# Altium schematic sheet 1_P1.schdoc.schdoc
size 309 x 223 mm; Symbol: Sheet-Symbol_A4; Device: Sheet-Symbol_A4; Company: 嘉立创EDA; Version: V1.0; Page Size: A4; @Project Name: ESP32C3电流表; @Page Count: 1; @Update Date: 2024-03-28; @Create Date: 2024-03-27; @Schematic Name: Schematic1; @Page No: 1; @Page Name: P1
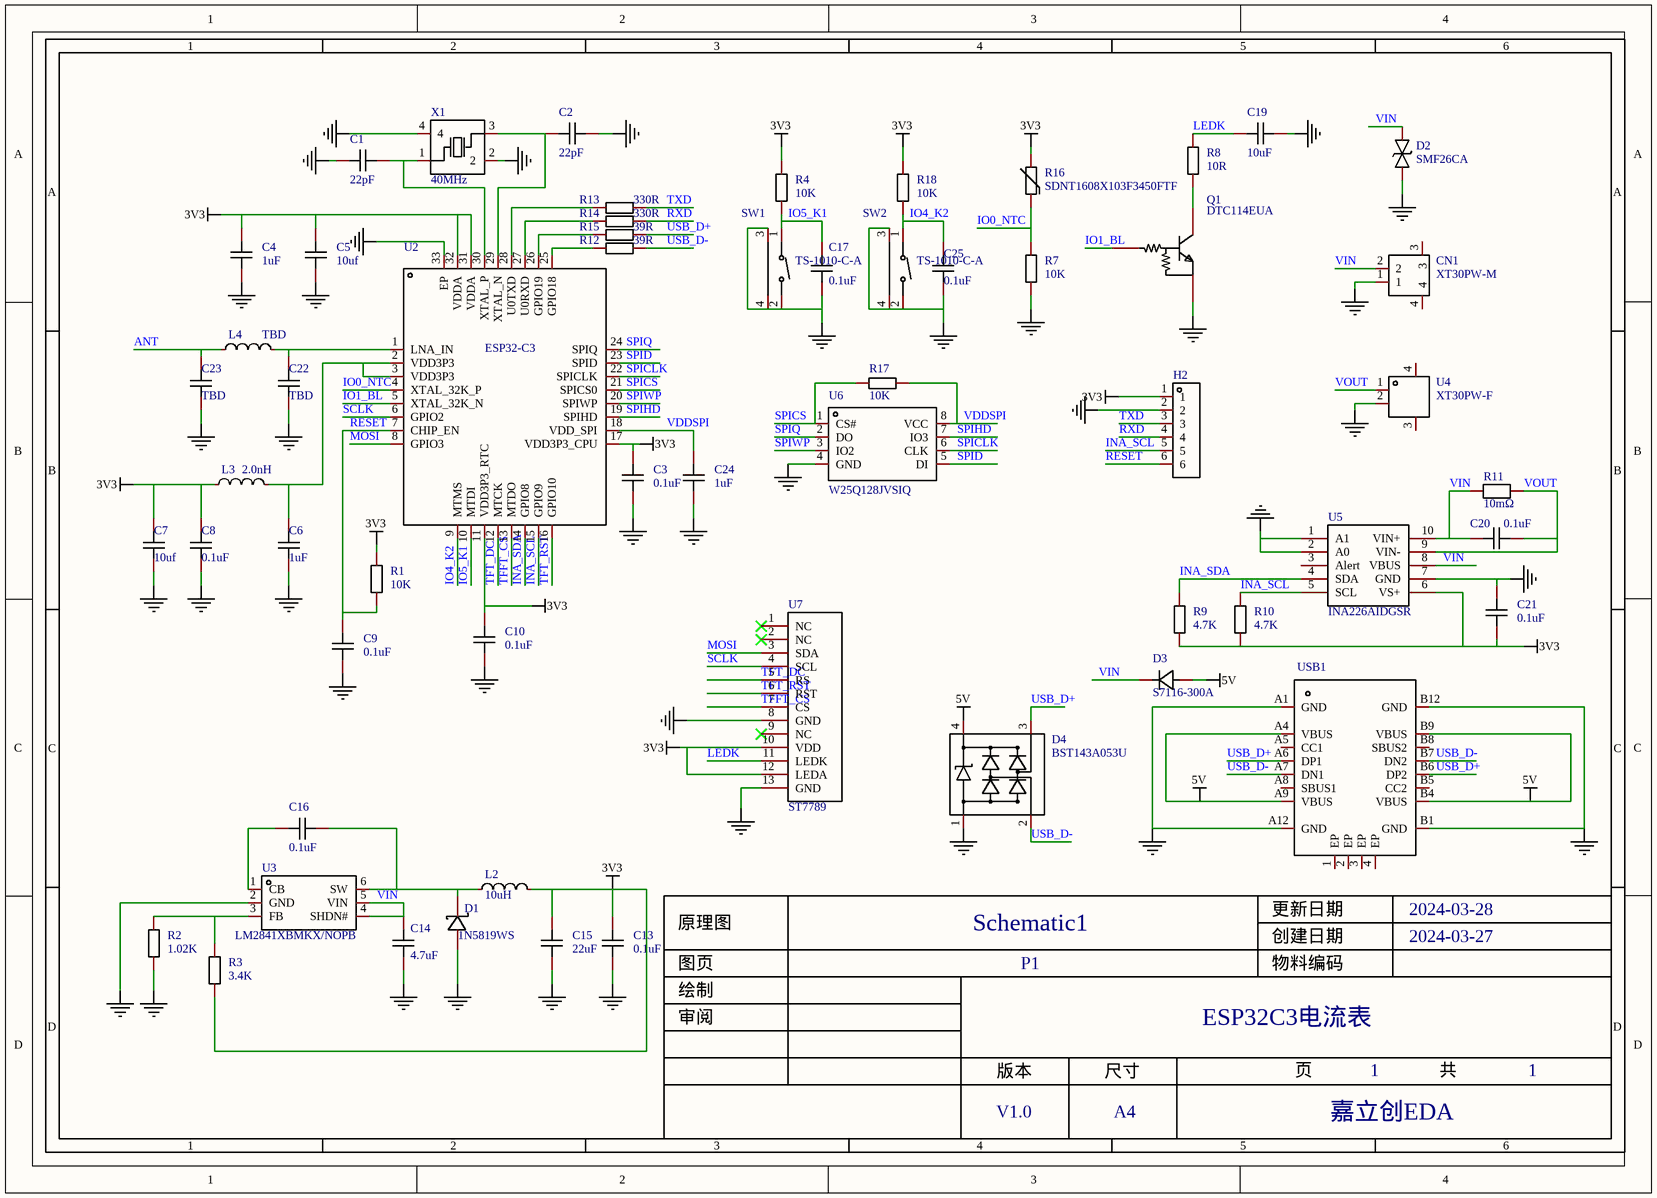
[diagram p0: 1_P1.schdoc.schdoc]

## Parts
C1  22pF  [C0603]
C2  22pF  [C0603]
C3  0.1uF  [C0603]
C4  1uF  [C0603]
C5  10uf  [C0603]
C6  1uF  [C0603]
C7  10uf  [C0603]
C8  0.1uF  [C0603]
C9  0.1uF  [C0603]
C10  0.1uF  [C0603]
C13  0.1uF  [C0603]
C14  4.7uF  [C0805]
C15  22uF  [C0805]
C16  0.1uF  [C0603]
C17  0.1uF  [C0603]
C19  10uF  [C0603]
C20  0.1uF  [C0603]
C21  0.1uF  [C0603]
C22  TBD  [C0603]
C23  TBD  [C0603]
C24  1uF  [C0603]
C25  0.1uF  [C0603]
CN1  XT30PW-M  [CONN-TH_XT30PW-M]
D1  1N5819WS  [SOD-323_L1.8-W1.3-LS2.5-RD]
D2  SMF26CA  [SOD-123_L2.8-W1.8-LS3.7-BI]
D3  S7116-300A  [SOD-323_L1.7-W1.3-LS2.5-RD]
D4  BST143A053U  [SOT-143_L2.9-W1.3-P1.92-LS2.3-BR]
H2  HDR-F_2.54_1x6P  [HDR-TH_6P-P2.54-V-F]  (value not drawn)
L2  10uH  [IND-SMD_L2.5-W2.0_FHD252012S-6R8MT]
L3  2.0nH  [L0603]
L4  TBD  [L0603]
Q1  DTC114EUA  [SOT-323-3_L2.0-W1.3-P1.30-LS2.1-BR]
R1  10K  [R0603]
R2  1.02K  [R0603]
R3  3.4K  [R0603]
R4  10K  [R0603]
R7  10K  [R0603]
R8  10R  [R0603]
R9  4.7K  [R0603]
R10  4.7K  [R0603]
R11  10mΩ  [R2512]
R12  39R  [R0603]
R13  330R  [R0603]
R14  330R  [R0603]
R15  39R  [R0603]
R16  SDNT1608X103F3450FTF  [R0603]
R17  10K  [R0603]
R18  10K  [R0603]
SW1  TS-1010-C-A  [KEY-SMD_TX-1010-X-X]
SW2  TS-1010-C-A  [KEY-SMD_TX-1010-X-X]
U2  ESP32-C3  [QFN-32_L5.0-W5.0-P0.50-TL-EP3.7]
U3  LM2841XBMKX/NOPB  [SOT-23-6_L2.9-W1.6-P0.95-LS2.8-BR]
U4  XT30PW-F  [CONN-TH_XT30PW-F-1]
U5  INA226AIDGSR  [MSOP-10_L3.0-W3.0-P0.50-LS5.0-BL]
U6  W25Q128JVSIQ  [SOIC-8_L5.3-W5.3-P1.27-LS8.0-BL]
U7  ST7789  [ST7789]
USB1  USB_TYPE-C-16P  [USB_TYPE-C-16P]  (value not drawn)
X1  40MHz  [OSC-SMD_4P-L3.2-W2.5-BL]

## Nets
3V3: C3.2 C4.2 C5.2 C7.2 C8.2 C10.2 C13.2 C15.2 C21.2 H2.1 L2.2 L3.1 R1.1 R3.1 R4.2 R9.1 R10.1 R16.2 R18.2 U2.11(VDD3P3_RTC) U2.17(VDD3P3_CPU) U2.31(VDDA) U2.32(VDDA) U5.6(VS+) U7.10(VDD) U7.12(LEDA)
5V: D3.2(A) D4.4 USB1.A4(VBUS) USB1.A9(VBUS) USB1.B4(VBUS) USB1.B9(VBUS)
GND: C1.1 C2.2 C3.1 C4.1 C5.1 C6.1 C7.1 C8.1 C9.2 C10.1 C13.1 C14.1 C15.1 C17.1 C19.1 C21.1 C22.1 C23.1 C24.1 C25.1 CN1.1 D1.2(A) D2.1 D4.1 H2.2 Q1.2(GND) R2.1 R7.1 SW1.2 SW1.3 SW1.4 SW2.2 SW2.3 SW2.4 U2.33(EP) U3.2(GND) U4.2 U5.1(A1) U5.2(A0) U5.7(GND) U6.4(GND) U7.8(GND) U7.13(GND) USB1.A1(GND) USB1.A12(GND) USB1.B1(GND) USB1.B12(GND) X1.2 X1.4
ANT: C23.2 L4.1
INA_SCL: H2.5 R10.2 U2.15(GPIO9) U5.5(SCL)
INA_SDA: R9.2 U2.14(GPIO8) U5.4(SDA)
IO0_NTC: R7.2 R16.1 U2.4(XTAL_32K_P)
IO1_BL: Q1.1(IN) U2.5(XTAL_32K_N)
IO4_K2: C25.2 R18.1 SW2.1 U2.9(MTMS)
IO5_K1: C17.2 R4.1 SW1.1 U2.10(MTDI)
LEDK: C19.2 R8.2 U7.11(LEDK)
MOSI: U2.8(GPIO3) U7.3(SDA)
RESET: C9.1 H2.6 R1.2 U2.7(CHIP_EN)
RXD: H2.4 R14.1
SCLK: U2.6(GPIO2) U7.4(SCL)
SPICLK: U2.22(SPICLK) U6.6(CLK)
SPICS: R17.1 U2.21(SPICS0) U6.1(CS#)
SPID: U2.23(SPID) U6.5(DI)
SPIHD: U2.19(SPIHD) U6.7(IO3)
SPIQ: U2.24(SPIQ) U6.2(DO)
SPIWP: U2.20(SPIWP) U6.3(IO2)
TFFT_CS: U2.13(MTDO) U7.7(CS)
TFT_DC: U2.12(MTCK) U7.5(RS)
TFT_RST: U2.16(GPIO10) U7.6(RST)
TXD: H2.3 R13.1
USB_D+: D4.3 R15.1 USB1.A6(DP1) USB1.B6(DP2)
USB_D-: D4.2 R12.1 USB1.A7(DN1) USB1.B7(DN2)
VDDSPI: C24.2 R17.2 U2.18(VDD_SPI) U6.8(VCC)
VIN: C14.2 C20.2 CN1.2 D2.2 D3.1(K) R11.1 U3.4(SHDN#) U3.5(VIN) U5.8(VBUS) U5.10(VIN+)
VOUT: C20.1 R11.2 U4.1 U5.9(VIN-)
NetC1_2: C1.2 U2.30(XTAL_P) X1.1(OSC1)
NetC2_1: C2.1 U2.29(XTAL_N) X1.3(OSC2)
NetC6_2: C6.2 L3.2 U2.2(VDD3P3) U2.3(VDD3P3)
NetC16_1: C16.1 D1.1(K) L2.1 U3.6(SW)
NetC16_2: C16.2 U3.1(CB)
NetC22_2: C22.2 L4.2 U2.1(LNA_IN)
NetQ1_3: Q1.3(OUT) R8.1
NetR2_2: R2.2 R3.2 U3.3(FB)
NetR12_2: R12.2 U2.25(GPIO18)
NetR13_2: R13.2 U2.28(U0TXD)
NetR14_2: R14.2 U2.27(U0RXD)
NetR15_2: R15.2 U2.26(GPIO19)

Not connected (* = marked no-connect by the designer): CN1 3 4; U4 3 4; U5 3(Alert); U7 1(NC)* 2(NC)* 9(NC)*; USB1 1(EP) 2(EP) 3(EP) 4(EP) A5(CC1) A8(SBUS1) B5(CC2) B8(SBUS2)

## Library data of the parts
C1-C10 C13 C16 C17 C19-C25 = CAP_0603: Symbol: CapAcitance; Convert to PCB: yes
C14 C15 = CAP_0805: Symbol: CapAcitance; Convert to PCB: yes
CN1 = XT30PW-M: Manufacturer: AMASS(艾迈斯); Add into BOM: yes; Brand: 艾迈斯; RatedVoltage: DC 500V; InterfaceType: 公头; RatedCurrent: 15A; RecommendedWireGauge: 16/18/20AWG; contact resistance: 1.2mΩ; specifications: 2pin; Description: 类别:-;类型1:-;
D1 = 1N5819WS_C191023: Manufacturer: Hottech(合科泰); Add into BOM: yes; Forward Voltage (Vf@If): 600mV@1A; Reverse Voltage (Vr): 40V; Average Rectified Current (Io): 1A; Description: 正向压降(Vf):600mV@1A;直流反向耐压(Vr):40V;平均整流电流(Io):1A;
D2 = SMF26CA_C435495: Manufacturer: AnBon(安邦); Add into BOM: yes; Reverse Stand-Off Voltage (Vrwm): 26V; Maximum Clamping Voltage: 42.1V; Peak Pulse Current (Ipp)@10/1000us: 4.8A; Breakdown Voltage: 28.9V; Type: TVS; Description: 反向截止电压(Vrwm):26V;最大钳位电压:42.1V;峰值脉冲电流(Ipp)@10/1000us:4.8A;击穿电压:28.9V;
D3 = S7116-300A: Manufacturer: MSKSEMI(美森科); Add into BOM: yes; Diode Configuration: 独立式; Forward Voltage (Vf@If): 500mV@1A; Reverse Voltage (Vr): 45V; Average Rectified Current (Io): 1A; Description: 二极管配置:独立式;正向压降(Vf):500mV@1A;直流反向耐压(Vr):45V;平均整流电流(Io):1A;
D4 = BST143A053U: Manufacturer: BORN(伯恩半导体); Add into BOM: yes; Reverse Stand-Off Voltage (Vrwm): 5V; Maximum Clamping Voltage: 25V; Peak Pulse Current (Ipp)@10/1000us: 12A@8/20us; Type: TVS; Description: 反向截止电压(Vrwm):5V;最大钳位电压:25V;峰值脉冲电流(Ipp)@10/1000us:12A@8/20us;
H2 = HDR-F_2.54_1x6P: Manufacturer: BOOMELE(博穆精密); Manufacturer Part: 2.54-1*6P母; Symbol: Header-Female-2.54_1x6; Convert to PCB: yes
L2 = FHD252012S-100MT: Manufacturer: cjiang(长江微电); Add into BOM: yes; Tolerance: ±20%; Rated Current: 1A; Saturation Current (Isat): 1.35A; DC Resistance (DCR): 435mΩ; Description: 电感值:10uH;精度:±20%;额定电流:1A;饱和电流(Isat):1.35A;
L3 L4 = L_0603: Symbol: SDFL1608S100KTF; Add into BOM: yes
Q1 = DTC114EUA_C55054: Manufacturer: CJ(江苏长电/长晶); Add into BOM: yes; Transistor Type: 1个NPN-预偏置; Collector-Emitter Breakdown Voltage (Vceo): 50V; Collector Current (Ic): 50mA; Power Dissipation (Pd): 200mW; Description: 晶体管类型:1个NPN-预偏置;集射极击穿电压(Vceo):50V;集电极电流(Ic):50mA;功率(Pd):200mW;
R1-R4 R7-R10 R12-R15 R17 R18 = Res_0603: Symbol: 电阻; Convert to PCB: yes
R11 = PA2512FKE7T0R01E: Manufacturer: YAGEO(国巨); Add into BOM: yes; Tolerance: ±1%; Power(Watts): 3W; Temperature Coefficient: ±50ppm/℃; Description: 电阻类型:采样电阻;阻值:10mΩ;精度:±1%;额定压降:-;功率:3W;温度系数:±50ppm/℃;安装方式:-;
R16 = SDNT1608X103F3450FTF: Manufacturer: Sunlord(顺络); Add into BOM: yes; Resistance @ 25℃: 10kΩ; B Constant (25℃/50℃): 3450K; Resistance Tolerance: ±1%; Power: 100mW; Steady State Current (Max): 310uA; Description: 阻值(25℃):10kΩ;B值(25℃/50℃):3450K;电阻精度:±1%;功率:100mW;B值精度:±1%;最大稳态电流(25℃):310uA;
SW1 SW2 = TS-1010-C-A: Manufacturer: XKB Connectivity(中国星坤); Add into BOM: yes; Circuit: 单刀单掷; Actuator Style: 矩形按钮; Operating Force: 260gf; Switch Length: 2.3mm; Switch Width: 4.7mm; Switch Height: 3.5mm; Strike Gundam: 不带; Contact Current: 50mA; Voltage Rating (DC): 12V; Actuator/Cap Color: 黑色; With Lamp: 无; Mechanical Life: 10万次; Description: 电路结构:单刀单掷;按钮形状:矩形按钮;作用力:260gf;安装方式:卧贴;开关长度:2.3mm;开关宽度:4.7mm;开关高度:3.5mm;带支架:不带;触点电流:50mA;额定电压(AC):-;额定电压(DC):12V;额定功率:-;绝缘电阻:-;带灯:无;机械寿命:10万次;
U2 = ESP32-C3: Manufacturer: ESPRESSIF(乐鑫); Add into BOM: yes; CPU Core: RISC-V; RAM Size: 400KB; GPIO Ports Number: 22; Operating Voltage Range: 3V~3.6V; CPU Maximum Speed: 160MHz; ADC (Bit): 12bit; UART/USART: 2; I2C: 1; SPI: 3; Peripheral/Function: 蓝牙协议栈；片载温度传感器；真随机数发生器；DMA；看门狗；WIFI协议栈；硬件密码算法引擎；54位Timer；PWM；RTC实时时钟; communication protocol: 蓝牙协议；WIFI协议; Watchdog: 有; Description: CPU内核:RISC-V;RAM总容量:400KB;GPIO端口数量:22;工作电压范围:3V~3.6V;CPU最大主频:160MHz;程序存储器类型:-;
U3 = LM2841XBMKX/NOPB: Manufacturer: TI(德州仪器); Add into BOM: yes; Function: 降压型; Switch tube (built-in/external): 内置; Description: 功能类型:降压型;输入电压:-;输出电流(最大值):-;
U4 = XT30PW-F: Manufacturer: AMASS(艾迈斯); Add into BOM: yes; Brand: 艾迈斯; InterfaceType: 母头; Description: 类别:-;类型1:-;
U5 = INA226AIDGSR: Manufacturer: TI(德州仪器); Add into BOM: yes; Supply Voltage: 0V~36V; Description: INA226 支持报警功能的 36V、双向、超高精度、低侧/高侧、I2C 输出电流/功率监控器
U6 = W25Q128JVSIQ: Manufacturer: WINBOND(华邦); Symbol: W25Q128JVSIQTR; Add into BOM: yes; Memory Size: 128Mbit; Description: 接口类型:-;存储容量:128Mbit;时钟频率(fc):-;
U7 = ST7789: Convert to PCB: yes
USB1 = USB_TYPE-C-16P: Add into BOM: yes
X1 = 1ZNY12000AB0C: Manufacturer: KDS(大真空); Add into BOM: yes; Description: 晶振类型:-;频率:-;外接负载电容:-;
